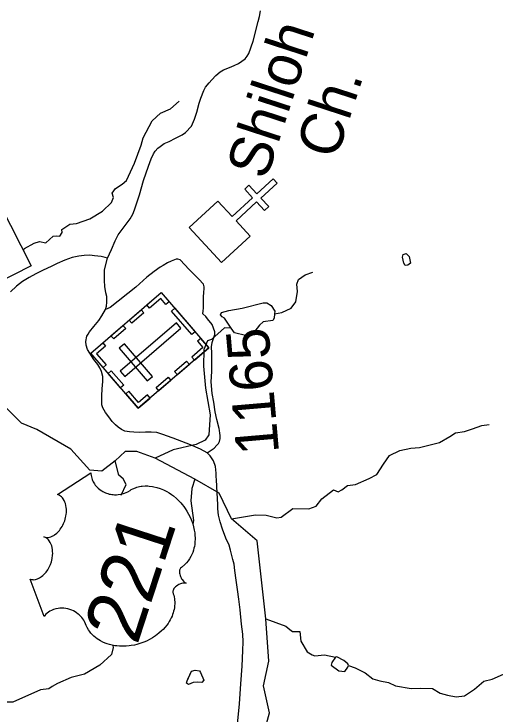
# Model space of a CAD drawing. Extents: x 1347947 to 1350662, y 1027710 to 1030532.
# Drawn here: x 1348295.7 to 1348346.4, y 1028931.2 to 1029005 of the extents above; entities that cross this region are included whole.
import ezdxf

# ---------------------------------------------------------------- set-up
doc = ezdxf.new("R2010")
doc.units = 0
doc.layers.add('Default', color=7, linetype='Continuous')
doc.layers.add('Prop Leader Line Light', color=7, linetype='Continuous')

msp = doc.modelspace()

# ---------------------------------------------------------------- linework, layer by layer
at = {"layer": 'Default'}
for points in [[(1348305.543, 1028979.226), (1348305.936, 1028980.161), (1348306.334, 1028981.072), (1348306.662, 1028981.703), (1348307.919, 1028983.397), (1348308.186, 1028983.86), (1348308.366, 1028984.35), (1348308.905, 1028985.902), (1348309.333, 1028987.425), (1348309.849, 1028988.934), (1348310.122, 1028989.724), (1348310.358, 1028990.244), (1348310.546, 1028990.515), (1348310.826, 1028990.832), (1348311.073, 1028991.011), (1348311.503, 1028991.317), (1348312.023, 1028991.523), (1348312.672, 1028991.897), (1348313.374, 1028992.238), (1348313.749, 1028992.494), (1348314.362, 1028993.139), (1348314.676, 1028993.9), (1348314.918, 1028994.633), (1348315.194, 1028995.565), (1348315.369, 1028996.105), (1348315.671, 1028996.903), (1348315.853, 1028997.259), (1348316.226, 1028997.718), (1348316.505, 1028998.02), (1348316.934, 1028998.491), (1348317.378, 1028998.892), (1348317.734, 1028999.093), (1348318.364, 1028999.323), (1348318.865, 1028999.536), (1348319.331, 1028999.761), (1348319.657, 1028999.995), (1348320.026, 1029000.239), (1348320.241, 1029000.518), (1348320.413, 1029000.818), (1348320.856, 1029002.101), (1348321.398, 1029004.178), (1348321.539, 1029004.7), (1348321.622, 1029005.32)], [(1348296.676, 1028980.036), (1348296.79, 1028980.26), (1348297.803, 1028980.822), (1348298.372, 1028980.992), (1348299.039, 1028980.859), (1348299.792, 1028981.553), (1348300.115, 1028981.604), (1348300.51, 1028981.567), (1348300.742, 1028981.936), (1348300.709, 1028982.252), (1348301.564, 1028982.831), (1348302.26, 1028982.893), (1348303.655, 1028983.383), (1348305.018, 1028984.191), (1348305.945, 1028985.09), (1348306.154, 1028985.628), (1348306.009, 1028986.087), (1348306.381, 1028986.569), (1348307.076, 1028987.04), (1348307.52, 1028987.434), (1348308.357, 1028989.242), (1348309.061, 1028991.137), (1348309.292, 1028991.913), (1348310.232, 1028993.725), (1348311.097, 1028994.503), (1348312.145, 1028994.993), (1348313.076, 1028995.788)], [(1348305.543, 1028979.226), (1348305.296, 1028979.329), (1348304.872, 1028979.4), (1348304.144, 1028979.502), (1348303.653, 1028979.573), (1348303.071, 1028979.538), (1348302.496, 1028979.457), (1348301.801, 1028979.314), (1348301.039, 1028979.036), (1348300.214, 1028978.667), (1348299.604, 1028978.374), (1348298.769, 1028977.974), (1348297.984, 1028977.592), (1348297.274, 1028977.197), (1348296.587, 1028976.771), (1348295.945, 1028976.276), (1348295.317, 1028975.686)], [(1348336.875, 1028978.467), (1348336.72, 1028978.725), (1348336.571, 1028979.347), (1348336.666, 1028979.62), (1348336.966, 1028979.719), (1348337.267, 1028979.411), (1348337.432, 1028978.719), (1348337.156, 1028978.511), (1348336.875, 1028978.467)], [(1348305.331, 1028973.835), (1348305.434, 1028974.2), (1348305.469, 1028974.592), (1348305.452, 1028974.816), (1348305.449, 1028975.191), (1348305.357, 1028975.582), (1348305.261, 1028976.248), (1348305.215, 1028976.893), (1348305.209, 1028977.385), (1348305.217, 1028977.996), (1348305.543, 1028979.226)], [(1348316.53, 1028970.363), (1348316.821, 1028971.206), (1348316.832, 1028971.493), (1348316.543, 1028972.24), (1348316.056, 1028972.833), (1348315.863, 1028973.078), (1348315.549, 1028973.363), (1348315.594, 1028973.687), (1348315.634, 1028973.963), (1348315.645, 1028975.223), (1348315.654, 1028975.545), (1348315.684, 1028975.716), (1348315.695, 1028975.954), (1348315.703, 1028976.208), (1348315.622, 1028976.492), (1348315.141, 1028977.03), (1348314.109, 1028978.063), (1348313.178, 1028979.08), (1348312.943, 1028979.148), (1348312.842, 1028979.149), (1348312.756, 1028979.139), (1348312.223, 1028978.919), (1348311.856, 1028978.742), (1348311.391, 1028978.483), (1348311.083, 1028978.301), (1348310.444, 1028977.848), (1348309.656, 1028977.225), (1348308.522, 1028976.192), (1348305.811, 1028974.036), (1348305.331, 1028973.835)], [(1348323.111, 1028973.37), (1348323.874, 1028973.511), (1348324.873, 1028973.977), (1348325.346, 1028974.627), (1348325.534, 1028975.745), (1348325.447, 1028976.488), (1348325.618, 1028976.978), (1348326.35, 1028977.498), (1348327.158, 1028977.765)], [(1348318.542, 1028971.85), (1348317.851, 1028972.907), (1348317.598, 1028973.058), (1348317.424, 1028973.261), (1348317.52, 1028973.533), (1348318.301, 1028973.729), (1348319.718, 1028973.987), (1348321.906, 1028974.527), (1348322.313, 1028974.527), (1348322.772, 1028974.264), (1348323.134, 1028973.668), (1348323.111, 1028973.37)], [(1348318.542, 1028971.85), (1348317.851, 1028972.907), (1348317.598, 1028973.058), (1348317.424, 1028973.261), (1348317.52, 1028973.533), (1348318.301, 1028973.729), (1348319.718, 1028973.987), (1348321.906, 1028974.527), (1348322.313, 1028974.527), (1348322.772, 1028974.264), (1348323.134, 1028973.668), (1348323.111, 1028973.37)], [(1348316.015, 1028958.741), (1348315.312, 1028959.128), (1348314.266, 1028959.584), (1348312.425, 1028960.278), (1348311.753, 1028960.512), (1348311.464, 1028960.613), (1348311.046, 1028960.757), (1348310.724, 1028960.862), (1348310.127, 1028960.89), (1348309.534, 1028960.911), (1348308.873, 1028960.884), (1348308.303, 1028960.92), (1348307.835, 1028960.937), (1348307.357, 1028961.007), (1348306.987, 1028961.177), (1348306.638, 1028961.437), (1348306.386, 1028961.671), (1348306.007, 1028962.048), (1348305.66, 1028962.514), (1348305.307, 1028962.964), (1348305.042, 1028963.467), (1348304.938, 1028963.794), (1348304.929, 1028964.062), (1348304.921, 1028964.736), (1348304.974, 1028965.472), (1348305.03, 1028966.258), (1348305.026, 1028966.782), (1348304.883, 1028967.285), (1348304.738, 1028967.681), (1348304.515, 1028968.037), (1348304.09, 1028968.572), (1348303.67, 1028969.215), (1348303.422, 1028969.603), (1348303.293, 1028970.063), (1348303.25, 1028970.466), (1348303.37, 1028971.015), (1348303.488, 1028971.24), (1348303.616, 1028971.473), (1348304.093, 1028972.032), (1348304.6, 1028972.67), (1348304.937, 1028973.159), (1348305.331, 1028973.835)], [(1348323.111, 1028973.37), (1348323.08, 1028972.931), (1348322.931, 1028972.678), (1348321.918, 1028972.523), (1348321.535, 1028972.188), (1348320.909, 1028971.388), (1348320.07, 1028971.09), (1348318.905, 1028971.375), (1348318.542, 1028971.85)], [(1348323.111, 1028973.37), (1348323.08, 1028972.931), (1348322.931, 1028972.678), (1348321.918, 1028972.523), (1348321.535, 1028972.188), (1348320.909, 1028971.388), (1348320.07, 1028971.09), (1348318.905, 1028971.375), (1348318.542, 1028971.85)], [(1348318.542, 1028971.85), (1348317.842, 1028971.89), (1348316.479, 1028970.676), (1348316.055, 1028970.517), (1348315.683, 1028969.628), (1348315.639, 1028967.87), (1348315.848, 1028965.553), (1348316.323, 1028962.716), (1348316.187, 1028960.641), (1348315.819, 1028960.057), (1348314.851, 1028959.621), (1348312.444, 1028959.036), (1348310.551, 1028958.17)], [(1348316.015, 1028958.741), (1348316.768, 1028959.218), (1348317.04, 1028959.544), (1348317.204, 1028959.711), (1348317.302, 1028959.915), (1348317.377, 1028960.247), (1348317.397, 1028960.564), (1348317.337, 1028960.816), (1348317.303, 1028961.072), (1348317.276, 1028961.286), (1348317.051, 1028962.229), (1348316.864, 1028963.041), (1348316.717, 1028964.08), (1348316.555, 1028964.987), (1348316.438, 1028966.203), (1348316.507, 1028967.309), (1348316.526, 1028968.12), (1348316.503, 1028969.215), (1348316.459, 1028969.889), (1348316.53, 1028970.363)], [(1348314.729, 1028955.952), (1348310.551, 1028958.17), (1348308.62, 1028958.866), (1348307.394, 1028958.858), (1348306.346, 1028957.895), (1348304.931, 1028956.807), (1348303.655, 1028956.896), (1348301.678, 1028959.118), (1348298.102, 1028961.201), (1348296.458, 1028961.856), (1348294.926, 1028963.406), (1348293.647, 1028965.371), (1348291.776, 1028966.388), (1348290.182, 1028966.255), (1348286.877, 1028967.331), (1348286.539, 1028967.138), (1348284.746, 1028967.283), (1348283.907, 1028967.913), (1348283.063, 1028968.023), (1348282.292, 1028968.439), (1348281.705, 1028968.575), (1348281.43, 1028968.724)], [(1348318.575, 1028951.791), (1348321.119, 1028952.185), (1348322.226, 1028952.144), (1348323.355, 1028951.872), (1348323.794, 1028951.963), (1348325.044, 1028952.851), (1348326.711, 1028952.838), (1348327.482, 1028953.118), (1348328.097, 1028953.883), (1348329.303, 1028954.827), (1348329.8, 1028954.612), (1348330.18, 1028954.825), (1348330.789, 1028955.285), (1348331.625, 1028955.399), (1348333.066, 1028956.017), (1348333.888, 1028956.443), (1348334.573, 1028957.529), (1348335.196, 1028958.433), (1348336.305, 1028958.982), (1348337.472, 1028959.227), (1348338.368, 1028959.281), (1348340.487, 1028959.802), (1348341.568, 1028960.444), (1348342.178, 1028960.843), (1348343.105, 1028960.987), (1348343.948, 1028961.242), (1348344.934, 1028961.611), (1348345.72, 1028961.702)], [(1348319.201, 1028930.147), (1348319.418, 1028932.294), (1348319.579, 1028934.399), (1348319.712, 1028936.247), (1348319.777, 1028937.896), (1348319.814, 1028938.821), (1348319.781, 1028939.606), (1348319.642, 1028940.673), (1348319.507, 1028942.197), (1348319.352, 1028943.326), (1348319.223, 1028944.314), (1348319.085, 1028945.32), (1348318.939, 1028946.339), (1348318.845, 1028946.992), (1348318.721, 1028947.505), (1348318.48, 1028948.472), (1348318.324, 1028948.987), (1348317.981, 1028949.74), (1348317.633, 1028950.675), (1348317.381, 1028951.468), (1348317.213, 1028952.166), (1348317.15, 1028952.846), (1348317.139, 1028953.273), (1348317.078, 1028954.512), (1348317.003, 1028955.867), (1348316.97, 1028956.245), (1348316.951, 1028956.594), (1348316.889, 1028957.295), (1348316.688, 1028957.9), (1348316.345, 1028958.402), (1348316.015, 1028958.741)], [(1348306.958, 1028954.27), (1348307.502, 1028955.403), (1348307.194, 1028955.979), (1348306.725, 1028956.388), (1348306.346, 1028957.895)], [(1348314.729, 1028955.952), (1348314.392, 1028954.988), (1348314.293, 1028953.658), (1348314.597, 1028951.613), (1348314.52, 1028951.185)], [(1348317.291, 1028954.496), (1348314.729, 1028955.952)], [(1348335.698, 1028918.15), (1348331.555, 1028919.691), (1348326.356, 1028922.525), (1348323.135, 1028925.184), (1348322.029, 1028926.424), (1348321.506, 1028927.313), (1348322.565, 1028931.326), (1348321.953, 1028934.176), (1348322.523, 1028936.782), (1348322.203, 1028941.242), (1348321.276, 1028949.448), (1348318.575, 1028951.791), (1348317.291, 1028954.496)], [(1348322.203, 1028941.242), (1348324.316, 1028940.462), (1348324.706, 1028940.122), (1348325.002, 1028939.915), (1348325.768, 1028939.892), (1348325.869, 1028938.898), (1348326.546, 1028937.743), (1348327.088, 1028937.431), (1348327.361, 1028937.336), (1348328.379, 1028937.449), (1348329.521, 1028937.212)], [(1348306.104, 1028938.438), (1348306.136, 1028938.221), (1348305.936, 1028937.474), (1348304.713, 1028936.373), (1348303.111, 1028935.405), (1348301.699, 1028935.042), (1348300.278, 1028934.419), (1348299.701, 1028934.111), (1348299.368, 1028933.86), (1348298.46, 1028933.77), (1348295.548, 1028932.444), (1348294.131, 1028932.471), (1348292.969, 1028932.531), (1348291.233, 1028932.057)], [(1348329.521, 1028937.212), (1348329.152, 1028936.627), (1348329.057, 1028936.354), (1348329.869, 1028935.764), (1348330.52, 1028935.699), (1348330.819, 1028936.146), (1348330.883, 1028936.328)], [(1348329.521, 1028937.212), (1348329.152, 1028936.627), (1348329.057, 1028936.354), (1348329.869, 1028935.764), (1348330.52, 1028935.699), (1348330.819, 1028936.146), (1348330.883, 1028936.328)], [(1348330.883, 1028936.328), (1348330.843, 1028936.504), (1348330.415, 1028936.857), (1348329.666, 1028937.222), (1348329.521, 1028937.212)], [(1348330.883, 1028936.328), (1348330.843, 1028936.504), (1348330.415, 1028936.857), (1348329.666, 1028937.222), (1348329.521, 1028937.212)], [(1348330.883, 1028936.328), (1348331.609, 1028936.073), (1348332.654, 1028935.563), (1348333.467, 1028934.912), (1348334.212, 1028934.713), (1348335.111, 1028934.541), (1348335.86, 1028934.177), (1348337.499, 1028933.909), (1348338.523, 1028933.917), (1348339.74, 1028933.9), (1348340.548, 1028933.413), (1348341.33, 1028933.199), (1348342.247, 1028933.021), (1348343.1, 1028933.13), (1348344.164, 1028933.839), (1348345.126, 1028934.665), (1348346.012, 1028934.864), (1348347.224, 1028935.419)], [(1348315.018, 1028934.581), (1348314.554, 1028934.54), (1348314.064, 1028934.303), (1348313.859, 1028934.476), (1348313.899, 1028934.707), (1348313.999, 1028934.876), (1348314.358, 1028935.729), (1348314.744, 1028935.84), (1348315.23, 1028935.771), (1348315.33, 1028935.593), (1348315.653, 1028934.766), (1348315.467, 1028934.525), (1348315.018, 1028934.581)], [(1348315.018, 1028934.581), (1348314.554, 1028934.54), (1348314.064, 1028934.303), (1348313.859, 1028934.476), (1348313.899, 1028934.707), (1348314.358, 1028935.729), (1348314.744, 1028935.84), (1348315.23, 1028935.771), (1348315.33, 1028935.593), (1348315.653, 1028934.766), (1348315.467, 1028934.525), (1348315.018, 1028934.581)]]:
    msp.add_lwpolyline(points, dxfattribs=at)
for points in [[(1348284.567, 1028971.87), (1348277.994, 1028984.789), (1348290.913, 1028991.362), (1348297.486, 1028978.443)], [(1348317.158, 1028985.248), (1348318.642, 1028983.637), (1348320.801, 1028985.616), (1348319.969, 1028986.524), (1348320.422, 1028986.939), (1348321.254, 1028986.031), (1348322.96, 1028987.595), (1348323.377, 1028987.141), (1348321.671, 1028985.577), (1348322.503, 1028984.669), (1348322.05, 1028984.254), (1348321.218, 1028985.162), (1348319.058, 1028983.182), (1348320.554, 1028981.544), (1348317.535, 1028978.776), (1348314.139, 1028982.481)], [(1348308.757, 1028963.419), (1348303.762, 1028969.226), (1348311.189, 1028975.615), (1348316.184, 1028969.808)], [(1348312.02, 1028974.648), (1348311.685, 1028974.36), (1348311.133, 1028975.002), (1348309.955, 1028973.988), (1348309.675, 1028974.313), (1348311.189, 1028975.615)], [(1348309.366, 1028973.47), (1348308.103, 1028972.383), (1348307.817, 1028972.715), (1348309.081, 1028973.802)], [(1348314.408, 1028971.196), (1348312.279, 1028973.671), (1348312.611, 1028973.957), (1348314.74, 1028971.482)], [(1348307.443, 1028971.817), (1348306.18, 1028970.73), (1348305.894, 1028971.062), (1348307.157, 1028972.149)], [(1348306.877, 1028967.334), (1348307.345, 1028966.789), (1348313.26, 1028971.877), (1348312.791, 1028972.422)], [(1348315.353, 1028970.771), (1348315.018, 1028970.483), (1348315.57, 1028969.841), (1348314.391, 1028968.827), (1348314.67, 1028968.503), (1348316.184, 1028969.805)], [(1348305.025, 1028970.316), (1348305.31, 1028969.985), (1348304.371, 1028969.177), (1348305.389, 1028967.994), (1348305.064, 1028967.715), (1348303.762, 1028969.229)], [(1348309.718, 1028966.317), (1348310.263, 1028966.786), (1348307.309, 1028970.22), (1348306.764, 1028969.751)], [(1348314.145, 1028968.052), (1348312.882, 1028966.965), (1348312.596, 1028967.297), (1348313.859, 1028968.384)], [(1348306.899, 1028965.58), (1348305.599, 1028967.092), (1348305.931, 1028967.378), (1348307.232, 1028965.866)], [(1348312.184, 1028966.366), (1348310.921, 1028965.279), (1348310.635, 1028965.611), (1348311.899, 1028966.698)], [(1348310.021, 1028964.506), (1348309.736, 1028964.837), (1348308.797, 1028964.029), (1348307.78, 1028965.212), (1348307.455, 1028964.933), (1348308.757, 1028963.419)], [(1348297.383, 1028945.418), (1348297.514, 1028945.384), (1348297.677, 1028945.365), (1348297.764, 1028945.363), (1348297.938, 1028945.386), (1348298.154, 1028945.445), (1348298.382, 1028945.553), (1348298.595, 1028945.689), (1348298.717, 1028945.788), (1348298.9, 1028945.963), (1348299.079, 1028946.17), (1348299.244, 1028946.413), (1348299.388, 1028946.669), (1348299.519, 1028946.958), (1348299.621, 1028947.252), (1348299.701, 1028947.579), (1348299.748, 1028947.954), (1348299.758, 1028948.131), (1348299.755, 1028948.334), (1348299.74, 1028948.525), (1348299.702, 1028948.743), (1348299.654, 1028948.923), (1348299.608, 1028949.067), (1348299.504, 1028949.284), (1348299.383, 1028949.469), (1348299.309, 1028949.554), (1348299.236, 1028949.63), (1348299.07, 1028949.757), (1348298.993, 1028949.802), (1348298.825, 1028949.871), (1348298.973, 1028949.835), (1348299.068, 1028949.82), (1348299.164, 1028949.815), (1348299.27, 1028949.821), (1348299.424, 1028949.844), (1348299.558, 1028949.882), (1348299.767, 1028949.967), (1348299.876, 1028950.027), (1348299.966, 1028950.086), (1348300.18, 1028950.249), (1348300.385, 1028950.456), (1348300.478, 1028950.56), (1348300.563, 1028950.67), (1348300.662, 1028950.813), (1348300.754, 1028950.964), (1348300.834, 1028951.116), (1348300.912, 1028951.274), (1348300.98, 1028951.439), (1348301.028, 1028951.575), (1348301.081, 1028951.745), (1348301.123, 1028951.904), (1348301.157, 1028952.07), (1348301.185, 1028952.256), (1348301.199, 1028952.408), (1348301.211, 1028952.611), (1348301.205, 1028952.8), (1348301.189, 1028952.97), (1348301.151, 1028953.195), (1348301.104, 1028953.383), (1348301.05, 1028953.527), (1348300.969, 1028953.704), (1348300.862, 1028953.881), (1348300.778, 1028953.991), (1348300.683, 1028954.081), (1348300.582, 1028954.169), (1348300.467, 1028954.24), (1348300.363, 1028954.29), (1348300.271, 1028954.323), (1348303.762, 1028956.627), (1348303.766, 1028956.545), (1348303.794, 1028956.349), (1348303.829, 1028956.189), (1348303.91, 1028955.926), (1348303.963, 1028955.807), (1348304.019, 1028955.687), (1348304.084, 1028955.573), (1348304.146, 1028955.47), (1348304.242, 1028955.339), (1348304.34, 1028955.218), (1348304.452, 1028955.094), (1348304.553, 1028954.997), (1348304.772, 1028954.82), (1348304.915, 1028954.723), (1348305.04, 1028954.65), (1348305.305, 1028954.523), (1348305.435, 1028954.47), (1348305.565, 1028954.428), (1348305.705, 1028954.39), (1348305.842, 1028954.36), (1348305.987, 1028954.339), (1348306.116, 1028954.322), (1348306.277, 1028954.312), (1348306.468, 1028954.311), (1348306.657, 1028954.324), (1348306.974, 1028954.379), (1348307.309, 1028954.472), (1348307.506, 1028954.552), (1348307.68, 1028954.637), (1348307.904, 1028954.777), (1348308.03, 1028954.851), (1348308.189, 1028954.931), (1348308.478, 1028955.052), (1348308.61, 1028955.096), (1348308.756, 1028955.137), (1348308.903, 1028955.171), (1348309.059, 1028955.201), (1348309.194, 1028955.222), (1348309.496, 1028955.245), (1348309.781, 1028955.24), (1348309.929, 1028955.233), (1348310.253, 1028955.191), (1348310.411, 1028955.164), (1348310.717, 1028955.091), (1348311.077, 1028954.975), (1348311.41, 1028954.836), (1348311.788, 1028954.642), (1348312.01, 1028954.511), (1348312.261, 1028954.339), (1348312.476, 1028954.181), (1348312.784, 1028953.924), (1348313, 1028953.714), (1348313.249, 1028953.452), (1348313.394, 1028953.281), (1348313.546, 1028953.087), (1348313.717, 1028952.851), (1348313.894, 1028952.582), (1348314.071, 1028952.27), (1348314.196, 1028952.024), (1348314.334, 1028951.711), (1348314.408, 1028951.525), (1348314.498, 1028951.264), (1348314.596, 1028950.915), (1348314.667, 1028950.579), (1348314.712, 1028950.298), (1348314.734, 1028950.055), (1348314.749, 1028949.745), (1348314.727, 1028949.245), (1348314.707, 1028949.066), (1348314.672, 1028948.858), (1348314.63, 1028948.667), (1348314.583, 1028948.483), (1348314.504, 1028948.241), (1348314.407, 1028948.006), (1348314.3, 1028947.789), (1348314.173, 1028947.568), (1348314.019, 1028947.344), (1348313.857, 1028947.148), (1348313.671, 1028946.957), (1348313.303, 1028946.651), (1348313.208, 1028946.559), (1348313.171, 1028946.502), (1348313.115, 1028946.355), (1348313.099, 1028946.206), (1348313.11, 1028946.044), (1348313.127, 1028945.943), (1348313.165, 1028945.804), (1348313.206, 1028945.693), (1348313.273, 1028945.553), (1348313.333, 1028945.452), (1348313.381, 1028945.375), (1348313.517, 1028945.211), (1348313.585, 1028945.146), (1348313.677, 1028945.071), (1348313.82, 1028944.985), (1348313.609, 1028945), (1348313.462, 1028944.985), (1348313.33, 1028944.954), (1348313.21, 1028944.917), (1348313.05, 1028944.85), (1348312.924, 1028944.783), (1348312.791, 1028944.696), (1348312.675, 1028944.596), (1348312.591, 1028944.513), (1348312.526, 1028944.432), (1348312.462, 1028944.329), (1348312.424, 1028944.24), (1348312.402, 1028944.164), (1348312.392, 1028944.052), (1348312.447, 1028943.879), (1348312.496, 1028943.715), (1348312.539, 1028943.541), (1348312.574, 1028943.338), (1348312.592, 1028943.193), (1348312.601, 1028943.023), (1348312.603, 1028942.827), (1348312.59, 1028942.62), (1348312.565, 1028942.411), (1348312.536, 1028942.229), (1348312.492, 1028942.038), (1348312.444, 1028941.869), (1348312.385, 1028941.695), (1348312.319, 1028941.536), (1348312.241, 1028941.352), (1348312.129, 1028941.129), (1348312.022, 1028940.948), (1348311.9, 1028940.76), (1348311.765, 1028940.571), (1348311.605, 1028940.373), (1348311.389, 1028940.13), (1348311.224, 1028939.966), (1348310.945, 1028939.714), (1348310.575, 1028939.432), (1348310.263, 1028939.23), (1348310.015, 1028939.088), (1348309.618, 1028938.89), (1348309.365, 1028938.781), (1348308.923, 1028938.623), (1348308.611, 1028938.532), (1348308.386, 1028938.48), (1348308.031, 1028938.412), (1348307.812, 1028938.383), (1348307.498, 1028938.355), (1348307.216, 1028938.345), (1348306.952, 1028938.345), (1348306.786, 1028938.354), (1348306.5, 1028938.382), (1348306.299, 1028938.407), (1348306.029, 1028938.457), (1348305.749, 1028938.527), (1348305.496, 1028938.605), (1348305.288, 1028938.68), (1348305.052, 1028938.783), (1348304.806, 1028938.909), (1348304.6, 1028939.031), (1348304.454, 1028939.128), (1348304.281, 1028939.257), (1348304.095, 1028939.415), (1348303.922, 1028939.585), (1348303.783, 1028939.739), (1348303.639, 1028939.922), (1348303.523, 1028940.094), (1348303.402, 1028940.309), (1348303.297, 1028940.526), (1348303.224, 1028940.717), (1348303.106, 1028940.955), (1348303.03, 1028941.083), (1348302.918, 1028941.245), (1348302.809, 1028941.379), (1348302.709, 1028941.491), (1348302.558, 1028941.645), (1348302.441, 1028941.746), (1348302.254, 1028941.886), (1348302.119, 1028941.97), (1348301.942, 1028942.068), (1348301.771, 1028942.15), (1348301.552, 1028942.232), (1348301.366, 1028942.286), (1348301.143, 1028942.332), (1348300.924, 1028942.359), (1348300.728, 1028942.369), (1348300.497, 1028942.359), (1348300.324, 1028942.337), (1348300.081, 1028942.284), (1348299.848, 1028942.213), (1348299.649, 1028942.127), (1348299.467, 1028942.034), (1348299.321, 1028941.935), (1348299.19, 1028941.839), (1348299.043, 1028941.712), (1348298.918, 1028941.584), (1348298.848, 1028941.5)]]:
    msp.add_lwpolyline(points, close=True, dxfattribs=at)

# ---------------------------------------------------------------- texts
for s, height, p in [('Shiloh', 4.5, (1348322.235, 1028987.372)), ('Ch.', 4.5, (1348329.59, 1028989.505)), ('221', 6.0021, (1348308.649, 1028938.387))]:
    msp.add_text(s, height=height, rotation=71.96667, dxfattribs=at).set_placement(p)
at = {"layer": 'Prop Leader Line Light'}
msp.add_text('1165', height=4.5, rotation=94.91364, dxfattribs=at).set_placement((1348323.594, 1028958.718))

doc.saveas('drawing.dxf')
